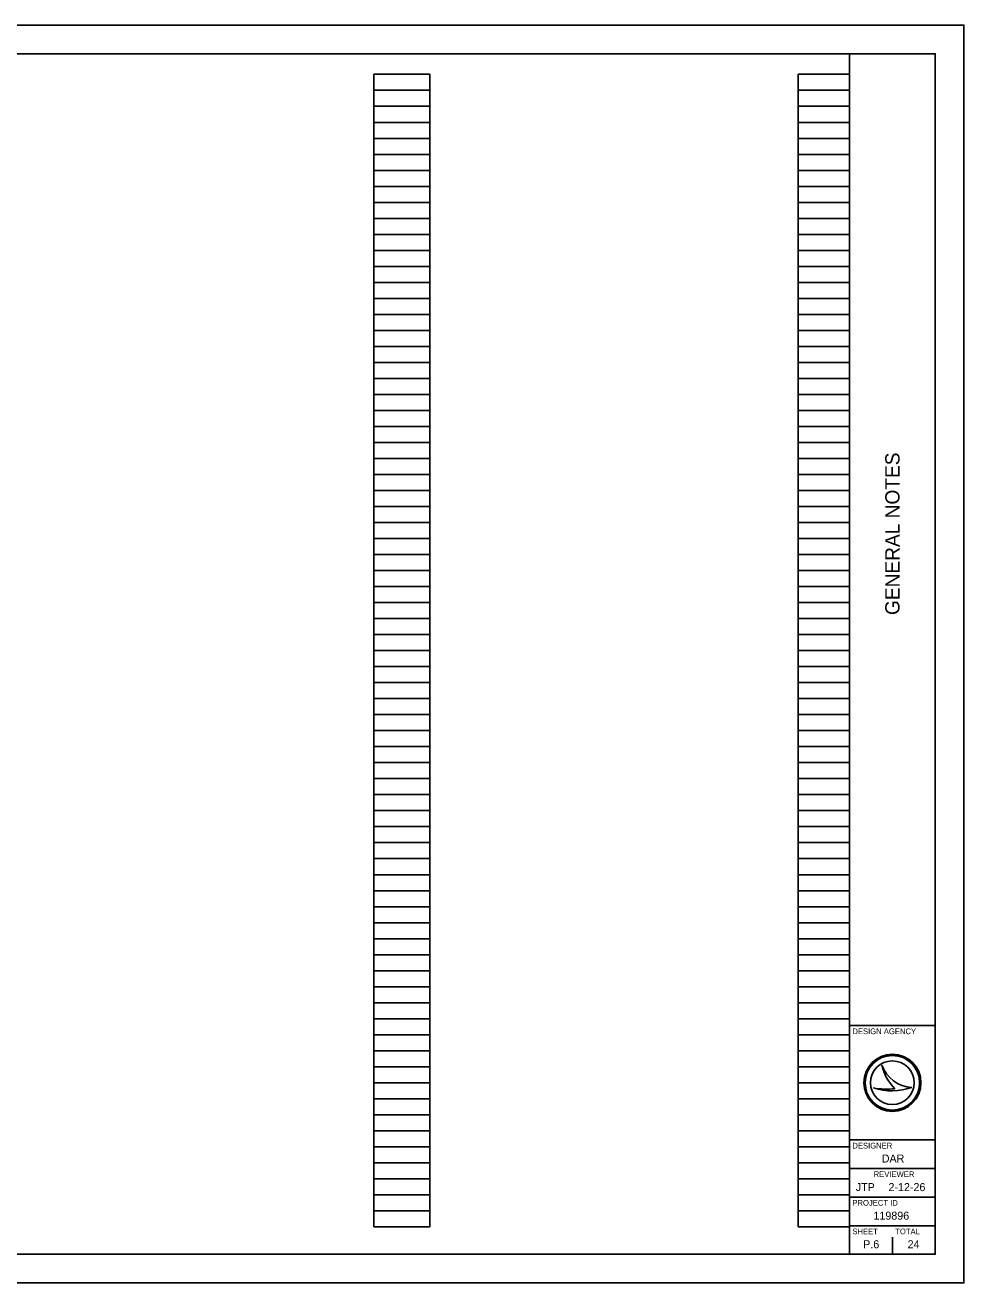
# Model space of a CAD drawing. Extents: x 0 to 34, y 0 to 22.
# Drawn here: x 17.58 to 34, y 0 to 22 of the extents above; entities that cross this region are included whole.
import ezdxf

# ---------------------------------------------------------------- set-up
doc = ezdxf.new("R2010")
doc.units = 0
for name, color, linetype in [('SH_Border', 7, 'Continuous'), ('SH_Cut_Line', 7, 'Continuous'), ('SH_Data', 7, 'Continuous')]:
    doc.layers.add(name, color=color, linetype=linetype)

msp = doc.modelspace()

# ---------------------------------------------------------------- linework, layer by layer
at = {"layer": 'SH_Border'}
for p, q in [((32, 0.5), (32, 21.5)), ((32, 4.5), (33.5, 4.5)), ((32, 2.5), (33.5, 2.5)), ((32, 2), (33.5, 2)), ((32, 1.5), (33.5, 1.5)), ((32, 1), (33.5, 1))]:
    msp.add_line(p, q, dxfattribs=at)
msp.add_lwpolyline([(1.5, 21.5), (33.5, 21.5), (33.5, 0.5), (1.5, 0.5)], close=True, dxfattribs=at)
at = {"layer": 'SH_Cut_Line'}
msp.add_lwpolyline([(0, 0), (34, 0), (34, 22), (0, 22)], close=True, dxfattribs=at)
at = {"layer": 'SH_Data'}
for p, q in [((23.68, 0.98), (23.68, 21.14)), ((23.68, 21.14), (24.66, 21.14)), ((24.66, 0.98), (24.66, 21.14)), ((31.1, 0.98), (31.1, 21.14)), ((31.1, 21.14), (32, 21.14)), ((32, 0.98), (32, 21.14)), ((23.68, 20.86), (24.66, 20.86)), ((31.1, 20.86), (32, 20.86)), ((23.68, 20.58), (24.66, 20.58)), ((31.1, 20.58), (32, 20.58)), ((23.68, 20.3), (24.66, 20.3)), ((31.1, 20.3), (32, 20.3)), ((23.68, 20.02), (24.66, 20.02)), ((31.1, 20.02), (32, 20.02)), ((23.68, 19.74), (24.66, 19.74)), ((31.1, 19.74), (32, 19.74)), ((23.68, 19.46), (24.66, 19.46)), ((31.1, 19.46), (32, 19.46)), ((23.68, 19.18), (24.66, 19.18)), ((31.1, 19.18), (32, 19.18)), ((23.68, 18.9), (24.66, 18.9)), ((31.1, 18.9), (32, 18.9)), ((23.68, 18.62), (24.66, 18.62)), ((31.1, 18.62), (32, 18.62)), ((23.68, 18.34), (24.66, 18.34)), ((31.1, 18.34), (32, 18.34)), ((23.68, 18.06), (24.66, 18.06)), ((31.1, 18.06), (32, 18.06)), ((23.68, 17.78), (24.66, 17.78)), ((31.1, 17.78), (32, 17.78)), ((23.68, 17.5), (24.66, 17.5)), ((31.1, 17.5), (32, 17.5)), ((23.68, 17.22), (24.66, 17.22)), ((31.1, 17.22), (32, 17.22)), ((23.68, 16.94), (24.66, 16.94)), ((31.1, 16.94), (32, 16.94)), ((23.68, 16.66), (24.66, 16.66)), ((31.1, 16.66), (32, 16.66)), ((23.68, 16.38), (24.66, 16.38)), ((31.1, 16.38), (32, 16.38)), ((23.68, 16.1), (24.66, 16.1)), ((31.1, 16.1), (32, 16.1)), ((23.68, 15.82), (24.66, 15.82)), ((31.1, 15.82), (32, 15.82)), ((23.68, 15.54), (24.66, 15.54)), ((31.1, 15.54), (32, 15.54)), ((23.68, 15.26), (24.66, 15.26)), ((31.1, 15.26), (32, 15.26)), ((23.68, 14.98), (24.66, 14.98)), ((31.1, 14.98), (32, 14.98)), ((23.68, 14.7), (24.66, 14.7)), ((31.1, 14.7), (32, 14.7)), ((23.68, 14.42), (24.66, 14.42)), ((31.1, 14.42), (32, 14.42)), ((23.68, 14.14), (24.66, 14.14)), ((31.1, 14.14), (32, 14.14)), ((23.68, 13.86), (24.66, 13.86)), ((31.1, 13.86), (32, 13.86)), ((23.68, 13.58), (24.66, 13.58)), ((31.1, 13.58), (32, 13.58)), ((23.68, 13.3), (24.66, 13.3)), ((31.1, 13.3), (32, 13.3)), ((23.68, 13.02), (24.66, 13.02)), ((31.1, 13.02), (32, 13.02)), ((23.68, 12.74), (24.66, 12.74)), ((31.1, 12.74), (32, 12.74)), ((23.68, 12.46), (24.66, 12.46)), ((31.1, 12.46), (32, 12.46)), ((23.68, 12.18), (24.66, 12.18)), ((31.1, 12.18), (32, 12.18)), ((23.68, 11.9), (24.66, 11.9)), ((31.1, 11.9), (32, 11.9)), ((23.68, 11.62), (24.66, 11.62)), ((31.1, 11.62), (32, 11.62)), ((23.68, 11.34), (24.66, 11.34)), ((31.1, 11.34), (32, 11.34)), ((23.68, 11.06), (24.66, 11.06)), ((31.1, 11.06), (32, 11.06)), ((23.68, 10.78), (24.66, 10.78)), ((31.1, 10.78), (32, 10.78)), ((23.68, 10.5), (24.66, 10.5)), ((31.1, 10.5), (32, 10.5)), ((23.68, 10.22), (24.66, 10.22)), ((31.1, 10.22), (32, 10.22)), ((23.68, 9.94), (24.66, 9.94)), ((31.1, 9.94), (32, 9.94)), ((23.68, 9.66), (24.66, 9.66)), ((31.1, 9.66), (32, 9.66)), ((23.68, 9.38), (24.66, 9.38)), ((31.1, 9.38), (32, 9.38)), ((23.68, 9.1), (24.66, 9.1)), ((31.1, 9.1), (32, 9.1)), ((23.68, 8.82), (24.66, 8.82)), ((31.1, 8.82), (32, 8.82)), ((23.68, 8.54), (24.66, 8.54)), ((31.1, 8.54), (32, 8.54)), ((23.68, 8.26), (24.66, 8.26)), ((31.1, 8.26), (32, 8.26)), ((23.68, 7.98), (24.66, 7.98)), ((31.1, 7.98), (32, 7.98)), ((23.68, 7.7), (24.66, 7.7)), ((31.1, 7.7), (32, 7.7)), ((23.68, 7.42), (24.66, 7.42)), ((31.1, 7.42), (32, 7.42)), ((23.68, 7.14), (24.66, 7.14)), ((31.1, 7.14), (32, 7.14)), ((23.68, 6.86), (24.66, 6.86)), ((31.1, 6.86), (32, 6.86)), ((23.68, 6.58), (24.66, 6.58)), ((31.1, 6.58), (32, 6.58)), ((23.68, 6.3), (24.66, 6.3)), ((31.1, 6.3), (32, 6.3)), ((23.68, 6.02), (24.66, 6.02)), ((31.1, 6.02), (32, 6.02)), ((23.68, 5.74), (24.66, 5.74)), ((31.1, 5.74), (32, 5.74)), ((23.68, 5.46), (24.66, 5.46)), ((31.1, 5.46), (32, 5.46)), ((23.68, 5.18), (24.66, 5.18)), ((31.1, 5.18), (32, 5.18)), ((23.68, 4.9), (24.66, 4.9)), ((31.1, 4.9), (32, 4.9)), ((23.68, 4.62), (24.66, 4.62)), ((31.1, 4.62), (32, 4.62)), ((23.68, 4.34), (24.66, 4.34)), ((31.1, 4.34), (32, 4.34)), ((23.68, 4.06), (24.66, 4.06)), ((31.1, 4.06), (32, 4.06)), ((23.68, 3.78), (24.66, 3.78)), ((31.1, 3.78), (32, 3.78)), ((32.567, 3.81), (32.567, 3.81)), ((23.68, 3.5), (24.66, 3.5)), ((31.1, 3.5), (32, 3.5)), ((32.417, 3.41), (32.417, 3.41)), ((32.75, 3.5), (32.75, 3.5)), ((33.087, 3.419), (33.087, 3.419)), ((23.68, 3.22), (24.66, 3.22)), ((31.1, 3.22), (32, 3.22)), ((23.68, 2.94), (24.66, 2.94)), ((31.1, 2.94), (32, 2.94)), ((23.68, 2.66), (24.66, 2.66)), ((31.1, 2.66), (32, 2.66)), ((23.68, 2.38), (24.66, 2.38)), ((31.1, 2.38), (32, 2.38)), ((23.68, 2.1), (24.66, 2.1)), ((31.1, 2.1), (32, 2.1)), ((23.68, 1.82), (24.66, 1.82)), ((31.1, 1.82), (32, 1.82)), ((23.68, 1.54), (24.66, 1.54)), ((31.1, 1.54), (32, 1.54)), ((23.68, 1.26), (24.66, 1.26)), ((31.1, 1.26), (32, 1.26)), ((23.68, 0.98), (24.66, 0.98)), ((31.1, 0.98), (32, 0.98)), ((32.375, 0.675), (32.375, 0.675)), ((32.75, 0.5), (32.75, 0.8))]:
    msp.add_line(p, q, dxfattribs=at)
for radius in [0.5, 0.477, 0.477, 0.382]:
    msp.add_circle((32.75, 3.5), radius, dxfattribs=at)
for centre, radius, start, end in [((33.116, 3.998), 0.58, 198.9257, 198.9319), ((33.347, 3.97), 0.796, 191.6379, 191.6421), ((33.116, 3.998), 0.58, 198.9319, 267.1657), ((33.347, 3.97), 0.796, 191.6421, 226.0947), ((32.739, 4.37), 1.013, 251.4576, 290.0832), ((32.648, 4.654), 1.266, 259.4964, 259.4995), ((32.739, 4.37), 1.013, 251.4527, 251.4576), ((32.648, 4.654), 1.266, 259.4995, 276.6672)]:
    msp.add_arc(centre, radius, start, end, dxfattribs=at)

# ---------------------------------------------------------------- texts
msp.add_text('GENERAL NOTES', height=0.25, rotation=90, dxfattribs=at).set_placement((32.875, 11.682))
for s, height, p in [('DESIGN AGENCY', 0.1, (32.05, 4.35)), ('DESIGNER', 0.1, (32.05, 2.35)), ('DAR', 0.14, (32.564, 2.105)), ('REVIEWER', 0.1, (32.422, 1.85)), ('JTP', 0.14, (32.109, 1.605)), ('2-12-26', 0.14, (32.682, 1.605)), ('PROJECT ID', 0.1, (32.05, 1.35)), ('119896', 0.14, (32.419, 1.105)), ('SHEET', 0.1, (32.05, 0.85)), ('TOTAL', 0.1, (32.8, 0.85)), ('P.6', 0.14, (32.239, 0.605)), ('24', 0.14, (33.016, 0.605))]:
    msp.add_text(s, height=height, dxfattribs=at).set_placement(p)

doc.saveas('drawing.dxf')
